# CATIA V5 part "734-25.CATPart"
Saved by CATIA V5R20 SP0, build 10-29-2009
Part number: 734-25
Bounding box of the stored display mesh (mm): x -24 to 24, y -23.94 to 23.94, z -30 to 50
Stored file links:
  C:\Users\Utente\Desktop\IO LAVORO\3D X SITO CF\X SITO\734\734-25.CATPart
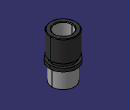
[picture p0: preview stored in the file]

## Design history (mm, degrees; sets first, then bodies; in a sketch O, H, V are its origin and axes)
Set1
  DatumSurface1 to DatumSurface25 "734-25"
Body1 (main body)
